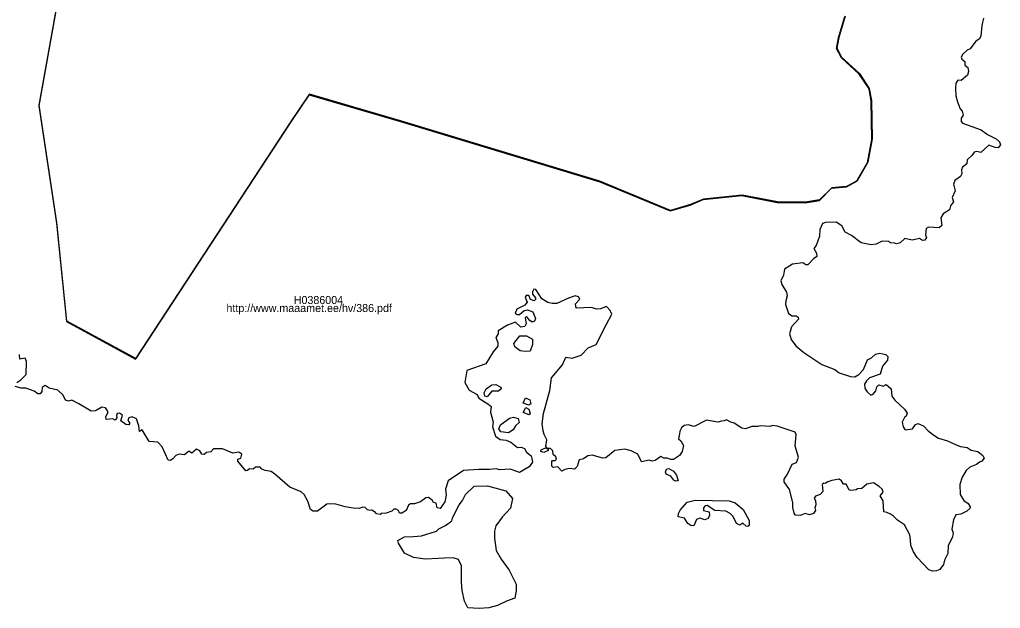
# Model space of a CAD drawing. Extents: x 369010 to 739155, y 6377141 to 6634081.
# Drawn here: x 440928 to 443990, y 6468889 to 6470728 of the extents above; entities that cross this region are included whole.
import ezdxf

# ---------------------------------------------------------------- set-up
doc = ezdxf.new("R2010")
doc.units = 0
for name, color, linetype in [('H_LINK', 7, 'Continuous'), ('H_PIIR', 7, 'Continuous'), ('H_TUNNUS', 7, 'Continuous')]:
    doc.layers.add(name, color=color, linetype=linetype)

msp = doc.modelspace()

# ---------------------------------------------------------------- linework, layer by layer
at = {"layer": 'H_PIIR'}
for points in [[(441043.1201, 6470766.8399), (440987.5399, 6470458.97), (441042.9599, 6470092.56), (441073.75, 6469784.66), (441289.2799, 6469667.6599), (441775.7699, 6470409.6999), (441831.6599, 6470493.06), (442116.39, 6470409.7801), (442738.6499, 6470221.75), (442958.6801, 6470130.5601), (443021.5001, 6470148.4001), (443061.7, 6470166), (443182.5601, 6470178.11), (443292.98, 6470156.84), (443380.23, 6470156.04), (443424.54, 6470163.3299), (443462.1999, 6470201), (443508.72, 6470205.4299), (443541.9401, 6470223.16), (443575.17, 6470280.78), (443588.46, 6470353.9), (443586.2399, 6470473.56), (443579.6, 6470511.2299), (443548.59, 6470557.77), (443493.21, 6470608.7299), (443477.71, 6470637.5399), (443484.3501, 6470670.78), (443504.29, 6470737.26)], [(443505.0838, 6470738.8475), (443485.1439, 6470672.3675), (443478.5038, 6470639.1274), (443494.0038, 6470610.3174), (443549.3838, 6470559.3575), (443580.3938, 6470512.8174), (443587.0337, 6470475.1475), (443589.2538, 6470355.4875), (443575.9638, 6470282.3675), (443542.7339, 6470224.7475), (443509.5138, 6470207.0174), (443462.9937, 6470202.5875), (443425.3338, 6470164.9174), (443381.0238, 6470157.6275), (443293.7738, 6470158.4275), (443183.3539, 6470179.6975), (443062.4938, 6470167.5875), (443022.2939, 6470149.9876), (442959.4739, 6470132.1476), (442739.4437, 6470223.3375), (442117.1838, 6470411.3676), (441832.4537, 6470494.6475), (441776.5637, 6470411.2874), (441290.0737, 6469669.2474), (441074.5438, 6469786.2475), (441043.7537, 6470094.1475), (440988.3337, 6470460.5575), (441043.9139, 6470768.4274)], [(443936.92, 6470732.3647), (443932.2, 6470709.3947), (443928.67, 6470676.4047), (443923.66, 6470666.3946), (443913.06, 6470660.5046), (443895.6901, 6470636.3546), (443885.68, 6470631.9447), (443872.4299, 6470620.1646), (443867.4201, 6470610.7347), (443869.49, 6470603.9646), (443878.3201, 6470596.8947), (443878.9101, 6470586.0046), (443888.0399, 6470578.0546), (443890.3999, 6470565.6847), (443886.57, 6470554.1947), (443867.4301, 6470537.7046), (443856.54, 6470538.5947), (443850.6501, 6470528.8746), (443849.76, 6470512.9746), (443850.94, 6470489.7046), (443855.36, 6470470.5647), (443864.04, 6470449.6547), (443870.8201, 6470441.9946), (443873.47, 6470429.3346), (443866.99, 6470420.2047), (443866.99, 6470409.9047), (443870.96, 6470404.8946), (443930.1499, 6470383.9847), (443948.99, 6470369.2646), (443976.67, 6470355.4246), (443986.39, 6470346.2947), (443989.6299, 6470337.1647), (443983.15, 6470327.7446), (443972.8399, 6470328.3246), (443953.71, 6470335.6946), (443928.38, 6470313.3146), (443916.17, 6470315.6646), (443907.6299, 6470314.1947), (443901.15, 6470304.4746), (443885.54, 6470290.0446), (443885.2501, 6470277.6747), (443871.4101, 6470267.0746), (443868.17, 6470258.5346), (443869.0499, 6470246.7546), (443865.5199, 6470237.9247), (443847.2601, 6470224.9646), (443843.1401, 6470214.0746), (443848.59, 6470193.1546), (443838.87, 6470172.5446), (443842.99, 6470158.9947), (443833.8599, 6470146.3346), (443830.63, 6470133.6746), (443811.19, 6470121.0046), (443803.3901, 6470108.3446), (443806.92, 6470084.7846), (443798.0899, 6470077.7246), (443765.1099, 6470080.0746), (443758.04, 6470075.6546), (443755.69, 6470055.6347), (443759.22, 6470047.6846), (443753.6299, 6470039.1446), (443746.8501, 6470038.5546), (443736.69, 6470044.1447), (443714.02, 6470038.8447), (443691.05, 6470043.8546), (443677.22, 6470031.1846), (443665.14, 6470027.6546), (443659.25, 6470030.0146), (443646.2999, 6470030.6046), (443640.7001, 6470035.3147), (443620.9801, 6470035.6046), (443601.54, 6470026.1847), (443585.94, 6470024.4247), (443555.02, 6470030.9047), (443524.6901, 6470053.8747), (443505.5499, 6470063.5947), (443494.22, 6470083.9147), (443477.43, 6470094.8047), (443443.2801, 6470094.2147), (443434.44, 6470091.5646), (443425.61, 6470072.4247), (443425.16, 6470051.5247), (443413.98, 6470022.9546), (443407.5001, 6470012.6446), (443415.15, 6469998.2146), (443416.92, 6469988.2047), (443405.7299, 6469980.8446), (443388.8, 6469961.9946), (443382.0299, 6469961.7046), (443372.9001, 6469968.1746), (443340.5099, 6469964.6446), (443316.07, 6469948.1546), (443312.2399, 6469929.6046), (443304.59, 6469911.6346), (443306.94, 6469901.0347), (443321.5199, 6469876.8846), (443323.58, 6469865.6947), (443320.05, 6469850.0847), (443319.1699, 6469838.0147), (443328, 6469810.6246), (443339.4801, 6469802.6746), (443352.1401, 6469802.9647), (443358.62, 6469798.5546), (443359.8, 6469792.0746), (443337.27, 6469768.8147), (443331.68, 6469746.7246), (443336.68, 6469728.7646), (443351.11, 6469708.7347), (443375.6999, 6469688.4146), (443432.53, 6469651.0146), (443473.01, 6469635.1147), (443486.5601, 6469625.1047), (443521.6, 6469613.3246), (443535.73, 6469612.4347), (443547.6599, 6469619.2146), (443562.0899, 6469635.1147), (443575.05, 6469665.7346), (443587.4099, 6469672.2146), (443600.07, 6469683.4047), (443613.62, 6469686.0546), (443631.58, 6469681.9346), (443637.7601, 6469675.4547), (443636.88, 6469664.5646), (443621.86, 6469645.7146), (443613.91, 6469620.6847), (443580.93, 6469608.9047), (443571.22, 6469600.3647), (443565.0301, 6469589.7646), (443566.2101, 6469576.5046), (443573.28, 6469565.0246), (443585.65, 6469555.6046), (443592.1199, 6469557.9546), (443600.37, 6469568.8546), (443603.9, 6469581.5146), (443609.79, 6469587.7047), (443623.48, 6469582.9947), (443633.49, 6469588.5846), (443648.22, 6469574.7446), (443650.57, 6469551.7746), (443660, 6469539.1147), (443690.1799, 6469511.7246), (443698.72, 6469499.0646), (443695.4801, 6469489.9346), (443689.88, 6469485.8146), (443683.4001, 6469470.7946), (443686.05, 6469456.0647), (443691.9399, 6469447.2346), (443715.6401, 6469450.1746), (443724.48, 6469463.4246), (443732.72, 6469466.6646), (443750.6799, 6469458.1246), (443764.23, 6469443.9947), (443782.19, 6469429.8546), (443796.76, 6469421.3146), (443824.1501, 6469412.7747), (443851.53, 6469399.8146), (443865.37, 6469394.5147), (443885.6899, 6469392.1647), (443898.64, 6469383.0346), (443918.96, 6469379.4947), (443934.57, 6469366.2447), (443938.9801, 6469358.2946), (443932.21, 6469349.4647), (443924.5501, 6469346.2246), (443915.43, 6469338.5646), (443893.9301, 6469330.3247), (443882.74, 6469319.7146), (443870.67, 6469299.1047), (443863.3101, 6469276.1347), (443864.19, 6469245.2146), (443875.3799, 6469226.3647), (443888.93, 6469217.2347), (443895.7001, 6469206.3447), (443894.5201, 6469201.6347), (443885.39, 6469193.0947), (443865.6701, 6469183.9646), (443850.36, 6469181.9046), (443843.29, 6469166.2946), (443838.29, 6469136.5547), (443841.82, 6469125.3646), (443840.35, 6469112.4046), (443826.21, 6469084.4247), (443825.63, 6469060.2847), (443814.7299, 6469039.6647), (443812.08, 6469026.4146), (443800.2999, 6469010.8047), (443789.9999, 6469006.3846), (443777.3401, 6469005.5047), (443766.15, 6469009.6247), (443729.64, 6469048.4946), (443718.15, 6469066.1647), (443710.2, 6469085.6047), (443709.3201, 6469103.5647), (443706.67, 6469119.1747), (443690.7699, 6469150.0946), (443668.68, 6469164.8247), (443656.32, 6469177.1846), (443646.8999, 6469183.9646), (443635.4101, 6469188.6746), (443625.7001, 6469191.0346), (443623.63, 6469225.1946), (443614.21, 6469240.7947), (443623.9301, 6469251.9847), (443620.3899, 6469261.7047), (443611.56, 6469269.9546), (443593.01, 6469281.4346), (443572.69, 6469276.7247), (443557.09, 6469263.1846), (443543.25, 6469262.5946), (443539.1301, 6469259.0546), (443522.9301, 6469257.5847), (443517.0399, 6469259.0546), (443508.21, 6469277.0246), (443499.96, 6469277.0246), (443493.78, 6469287.3246), (443486.5601, 6469292.3347), (443463.3, 6469288.5046), (443450.93, 6469284.9746), (443442.98, 6469279.3746), (443438.27, 6469279.9646), (443433.5601, 6469276.4346), (443435.03, 6469254.0546), (443426.4899, 6469244.6246), (443412.51, 6469240.2147), (443408.6801, 6469233.4347), (443412.2201, 6469226.0746), (443413.1, 6469212.2346), (443410.16, 6469203.1046), (443412.51, 6469194.8647), (443406.03, 6469185.4347), (443393.96, 6469181.6047), (443380.12, 6469185.1446), (443364.2201, 6469179.8447), (443350.3801, 6469180.4347), (443345.6699, 6469186.6147), (443342.14, 6469203.9847), (443342.14, 6469220.1847), (443331.54, 6469260.5347), (443314.6101, 6469284.3846), (443314.31, 6469292.9247), (443325.4999, 6469308.5347), (443339.05, 6469339.7446), (443352.88, 6469345.3447), (443359.6601, 6469361.2446), (443348.6199, 6469395.7046), (443352.1501, 6469431.9247), (443348.6199, 6469439.8747), (443292.52, 6469458.7246), (443278.68, 6469460.1947), (443270.7299, 6469456.9546), (443239.82, 6469459.3146), (443231.87, 6469457.2547), (443214.05, 6469457.2547), (443194.0301, 6469450.4747), (443182.5401, 6469451.9546), (443158.99, 6469468.1447), (443147.7999, 6469470.7946), (443134.6901, 6469478.4546), (443127.33, 6469475.2147), (443119.0801, 6469474.0347), (443107.6, 6469470.7946), (443071.6799, 6469476.6846), (443033.84, 6469456.9546), (443014.7, 6469462.2546), (443002.3399, 6469460.4846), (442993.8001, 6469452.8246), (442988.4999, 6469442.8147), (442988.2, 6469433.9846), (442984.6701, 6469418.9646), (442992.33, 6469412.4846), (443000.28, 6469398.3447), (442995.86, 6469379.5047), (442987.32, 6469366.2546), (442969.0701, 6469353.8847), (442960.53, 6469353.8847), (442949.05, 6469358.2946), (442939.0401, 6469358.5947), (442929.62, 6469363.6046), (442911.3601, 6469351.5246), (442902.23, 6469349.4647), (442893.3999, 6469351.8246), (442869.3444, 6469347.0909), (442857.5645, 6469370.941), (442836.9544, 6469381.5409), (442816.6444, 6469386.551), (442786.3144, 6469381.841), (442757.7545, 6469359.7509), (442748.9143, 6469358.281), (442715.4943, 6469367.4109), (442701.9544, 6469365.941), (442688.4043, 6469356.2209), (442674.8644, 6469352.6909), (442668.6843, 6469332.371), (442660.4344, 6469324.1309), (442643.9443, 6469325.891), (442629.5143, 6469322.651), (442620.9745, 6469318.2409), (442607.7245, 6469330.9009), (442593.8845, 6469329.7209), (442589.1745, 6469333.551), (442588.8844, 6469347.6809), (442590.9445, 6469351.511), (442599.1944, 6469351.511), (442603.3144, 6469355.6309), (442602.1344, 6469362.7009), (442593.0044, 6469369.4709), (442592.1245, 6469381.5509), (442585.0543, 6469388.911), (442576.2244, 6469388.911), (442570.0443, 6469395.0909), (442573.23, 6469416), (442565.49, 6469432.18), (442562.7, 6469443.8), (442559.16, 6469465.5), (442563.0208, 6469498.3929), (442583.13, 6469569.27), (442588.4208, 6469609.5181), (442622.2875, 6469649.7349), (442633.11, 6469674.18), (442652.2401, 6469670.7547), (442680.51, 6469680.48), (442703.01, 6469702.5), (442727.49, 6469712.91), (442759.342, 6469774.883), (442776.7029, 6469808.1676), (442771.2483, 6469819.8623), (442759.4299, 6469831.8247), (442740.87, 6469824.4646), (442728.65, 6469823.5847), (442713.3399, 6469828.5846), (442665.35, 6469826.8246), (442662.7001, 6469840.3647), (442676.24, 6469855.0946), (442673.0001, 6469862.1646), (442662.1101, 6469865.3946), (442641.5, 6469858.3347), (442605.28, 6469841.5447), (442589.9701, 6469840.9547), (442576.43, 6469844.7846), (442557.88, 6469855.6846), (442539.6199, 6469884.8347), (442532.56, 6469885.7246), (442528.43, 6469877.4746), (442529.02, 6469870.1146), (442537.86, 6469858.9247), (442538.4499, 6469853.9146), (442534.0301, 6469850.0847), (442523.13, 6469854.2147), (442516.95, 6469866.5746), (442509.3, 6469866.2847), (442505.7601, 6469860.6847), (442511.9499, 6469845.0847), (442505.1701, 6469835.6547), (442479.56, 6469824.1747), (442475.1401, 6469811.2146), (442481.03, 6469806.5046), (442488.3901, 6469807.3847), (442502.52, 6469819.4646), (442513.1199, 6469821.2246), (442529.9101, 6469815.0447), (442538.74, 6469795.0146), (442535.2101, 6469785.8946), (442527.5499, 6469783.5346), (442520.7801, 6469787.9547), (442510.47, 6469800.9046), (442505.7601, 6469796.4947), (442509.44, 6469777.3546), (442504.4399, 6469769.4047), (442492.66, 6469767.3446), (442475.29, 6469782.9446), (442450.55, 6469773.8146), (442421.3999, 6469756.4446), (442421.5501, 6469746.4347), (442414.78, 6469734.9446), (442420.67, 6469719.9247), (442420.67, 6469708.1447), (442405.65, 6469690.1846), (442383.1037, 6469652.6453), (442324.3661, 6469632.0077), (442317.91, 6469594.4747), (442331.14, 6469571.1346), (442356.46, 6469556.9947), (442360.8701, 6469545.5147), (442389.7201, 6469527.5547), (442399.4399, 6469519.6047), (442398.2599, 6469501.6447), (442406.5001, 6469471.3146), (442403.85, 6469456.0047), (442413.2663, 6469427.2198), (442428, 6469416.2547), (442446.2601, 6469414.4847), (442460.97, 6469408.0046), (442481.58, 6469391.5147), (442493.36, 6469392.4046), (442504.25, 6469388.8646), (442509.85, 6469376.7946), (442525.15, 6469365.6047), (442526.3299, 6469357.6546), (442528.8431, 6469346.1412), (442518.2598, 6469330.9276), (442488.4941, 6469313.7297), (442479.9541, 6469317.2696), (442459.3899, 6469323.6516), (442442.6099, 6469322.7715), (442426.9468, 6469322.11), (442415.0721, 6469324.9745), (442394.5668, 6469322.9901), (442361.5968, 6469322.9901), (442313.7568, 6469319.4601), (442265.5822, 6469287.9327), (442257.0901, 6469261.3646), (442259.44, 6469243.1147), (442255.62, 6469222.5047), (442240.6, 6469201.3046), (442231.48, 6469203.6546), (442227.94, 6469217.4946), (442219.4099, 6469220.4446), (442215.28, 6469227.2146), (442204.69, 6469235.4546), (442195.41, 6469234.2846), (442179.51, 6469222.5047), (442160.96, 6469216.0247), (442148.0101, 6469216.3246), (442141.5299, 6469211.9046), (442134.7601, 6469194.8247), (442120.9301, 6469186.8746), (442113.4301, 6469187.1747), (442110.19, 6469195.4147), (442103.4199, 6469199.5346), (442095.76, 6469198.6546), (442089.29, 6469192.7646), (442071.92, 6469187.1747), (442057.49, 6469185.6946), (442053.66, 6469182.7547), (442042.18, 6469184.2246), (442038.9401, 6469188.6446), (442027.03, 6469195.7146), (442021.73, 6469194.5346), (442014.0799, 6469196.5947), (442006.72, 6469204.2546), (441999.36, 6469205.7247), (441987.87, 6469201.3046), (441969.0299, 6469202.1947), (441944.01, 6469206.3147), (441914.7299, 6469214.8547), (441896.18, 6469215.7446), (441886.4599, 6469214.2647), (441857.1801, 6469192.7746), (441844.5201, 6469192.4847), (441835.39, 6469198.3746), (441827.7401, 6469223.6947), (441815.96, 6469245.1846), (441807.13, 6469253.7247), (441771.36, 6469267.8646), (441724.26, 6469308.7946), (441712.48, 6469316.4547), (441693.7799, 6469319.3947), (441683.77, 6469324.1047), (441678.7599, 6469330.2947), (441663.7499, 6469330.2947), (441656.3901, 6469323.8146), (441645.2, 6469325.5846), (441639.0199, 6469319.3947), (441633.72, 6469319.1046), (441608.7, 6469349.1346), (441608.7, 6469355.3246), (441618.7, 6469358.5647), (441621.35, 6469370.9246), (441611.9301, 6469377.1147), (441592.9401, 6469373.8646), (441561.44, 6469387.1146), (441532.45, 6469388.0047), (441524.5, 6469377.9946), (441511.26, 6469376.2246), (441503.31, 6469370.3346), (441496.5401, 6469371.2147), (441490.06, 6469381.2247), (441480.05, 6469386.5246), (441465.3299, 6469374.1647), (441455.6101, 6469380.3446), (441442.8199, 6469369.1546), (441425.74, 6469371.2147), (441415.1399, 6469367.0946), (441406.0201, 6469355.9046), (441398.3599, 6469350.9046), (441391.5901, 6469352.0846), (441372.4499, 6469393.8947), (441359.5, 6469408.0246), (441332.5999, 6469410.7146), (441309.89, 6469446.4846), (441301.4699, 6469441.8546), (441300.21, 6469459.5247), (441292.43, 6469481.4147), (441279.39, 6469487.7246), (441268.87, 6469483.9347), (441265.93, 6469475.9446), (441271.3999, 6469467.9446), (441268.87, 6469462.8946), (441259.2, 6469463.7447), (441244.05, 6469475.1047), (441248.68, 6469492.3547), (441239.8501, 6469499.0846), (441231.85, 6469497.3946), (441229.75, 6469491.9247), (441231.43, 6469483.9347), (441225.54, 6469477.2046), (441218.3899, 6469480.9947), (441197.78, 6469478.8846), (441196.94, 6469487.3047), (441203.67, 6469503.2846), (441195.68, 6469515.4947), (441183.9001, 6469517.1747), (441164.34, 6469505.8147), (441150.8799, 6469504.9746), (441113.02, 6469527.6947), (441090.2999, 6469539.4746), (441080.6201, 6469536.1046), (441071.3701, 6469539.4746), (441063.38, 6469554.6146), (441046.76, 6469571.0147), (441020.25, 6469576.9146), (441007.2099, 6469584.9047), (440998.38, 6469579.0147), (440997.12, 6469566.8147), (440991.6499, 6469558.8147), (440984.92, 6469558.8147), (440973.56, 6469567.2346), (440947.48, 6469576.4846), (440932.3301, 6469576.9146), (440913.4, 6469582.3847)], [(440918.4501, 6469595.0046), (440931.91, 6469602.9946), (440947.9001, 6469619.4047), (440948.74, 6469659.7947), (440944.9501, 6469671.1546), (440928.54, 6469667.7947), (440927.28, 6469682.5146)]]:
    msp.add_lwpolyline(points, dxfattribs=at)
for points in [[(442490.1185, 6469693.6707), (442473.582, 6469705.5769), (442470.2747, 6469716.8218), (442489.4571, 6469740.6343), (442509.9623, 6469739.9728), (442528.4832, 6469730.0509), (442528.4832, 6469713.5145), (442521.2071, 6469693.0092), (442505.9935, 6469691.0248)], [(442414.1747, 6469588.6396), (442430.0631, 6469580.1989), (442430.8906, 6469574.9027), (442422.9464, 6469567.4551), (442401.4308, 6469567.124), (442387.032, 6469550.4081), (442380.5774, 6469552.2288), (442377.5983, 6469562.1589), (442384.0529, 6469574.5718), (442401.7619, 6469586.9846)], [(442517.1181, 6469523.7619), (442499.4093, 6469530.0511), (442507.0223, 6469546.436), (442520.0972, 6469540.3123), (442523.2418, 6469528.5615)], [(442518.2767, 6469494.1368), (442499.4093, 6469501.088), (442508.5119, 6469516.1489), (442517.1181, 6469511.1836), (442521.2557, 6469498.4398)], [(442469.2874, 6469486.1926), (442484.3484, 6469482.0549), (442487.493, 6469469.3111), (442475.7422, 6469459.7119), (442468.6255, 6469446.6372), (442454.2266, 6469437.0379), (442430.0631, 6469440.8445), (442424.2703, 6469449.6162), (442428.9045, 6469462.029), (442456.8747, 6469483.5445)], [(442569.4175, 6469390.3658), (442578.1892, 6469386.5591), (442578.1892, 6469381.925), (442563.7902, 6469375.967), (442555.184, 6469379.6079), (442555.846, 6469384.9041)], [(442976.5572, 6469286.2638), (442969.9371, 6469289.5738), (442960.9998, 6469302.4832), (442945.9389, 6469308.1103), (442943.953, 6469314.8959), (442947.263, 6469323.6676), (442954.8763, 6469325.6537), (442968.613, 6469318.0405), (442978.7088, 6469305.4622), (442984.005, 6469288.0843)], [(442319.9542, 6469245.2024), (442346.4126, 6469270.9994), (442388.746, 6469272.3223), (442445.6315, 6469256.4473), (442466.7982, 6469232.6347), (442460.1836, 6469202.2076), (442434.3867, 6469173.7648), (442414.5429, 6469147.3064), (442409.9127, 6469130.1085), (442410.5742, 6469108.9418), (442415.2044, 6469069.9156), (442431.0794, 6469043.4572), (442455.5534, 6469009.0613), (442478.043, 6468964.7435), (442478.043, 6468944.2383), (442473.4128, 6468921.0872), (442447.6159, 6468911.8268), (442419.1731, 6468897.9361), (442392.7147, 6468890.6601), (442362.2876, 6468889.3371), (442327.2302, 6468891.3215), (442316.6469, 6468911.8268), (442309.3708, 6468944.8998), (442307.3865, 6468971.3581), (442307.3865, 6468989.879), (442307.3865, 6469002.4468), (442306.725, 6469022.2905), (442298.126, 6469042.1343), (442280.9281, 6469046.7645), (442254.4697, 6469046.1031), (442234.6259, 6469044.7802), (442194.2769, 6469043.4572), (442157.2351, 6469048.0875), (442129.4538, 6469061.3167), (442110.2715, 6469093.0667), (442108.2871, 6469101.0042), (442128.7923, 6469112.9105), (442157.2351, 6469114.2334), (442182.3706, 6469115.5564), (442228.6728, 6469130.7699), (442236.6103, 6469137.3845), (442257.1155, 6469148.6293), (442276.9593, 6469162.52), (442279.6051, 6469171.119), (442288.8656, 6469190.9628), (442300.1104, 6469212.7909), (442310.0323, 6469226.6816)], [(443201.3116, 6469145.4198), (443195.6845, 6469145.7509), (443185.7543, 6469155.5156), (443176.3206, 6469149.5575), (443165.3973, 6469154.5226), (443155.467, 6469176.7001), (443146.0333, 6469185.8029), (443132.462, 6469192.5885), (443098.3682, 6469194.9055), (443074.2046, 6469210.2975), (443067.5845, 6469209.6355), (443062.2883, 6469203.5118), (443062.6192, 6469195.2367), (443079.9972, 6469191.0989), (443081.8178, 6469180.8377), (443076.8526, 6469169.5835), (443067.4188, 6469165.4459), (443051.1996, 6469171.073), (443041.2692, 6469167.2664), (443032.8287, 6469147.5714), (443023.5604, 6469148.068), (443013.9612, 6469154.8536), (443003.0379, 6469170.7419), (442983.8393, 6469175.5417), (442984.5014, 6469185.4718), (442990.1285, 6469196.0642), (443012.1405, 6469221.0551), (443036.3042, 6469227.3443), (443143.0542, 6469225.5238), (443161.0941, 6469218.7381), (443186.9128, 6469198.2156), (443205.7803, 6469163.6252), (443205.1182, 6469148.3989)]]:
    msp.add_lwpolyline(points, close=True, dxfattribs=at)

# ---------------------------------------------------------------- texts
at = {"layer": 'H_LINK'}
msp.add_text('http://www.maaamet.ee/hv/386.pdf', height=25, rotation=0, dxfattribs=at).set_placement((441573.3956, 6469814.6987))
at = {"layer": 'H_TUNNUS'}
msp.add_text('H0386004', height=25, rotation=0, dxfattribs=at).set_placement((441783.3749, 6469839.6987))

doc.saveas('drawing.dxf')
